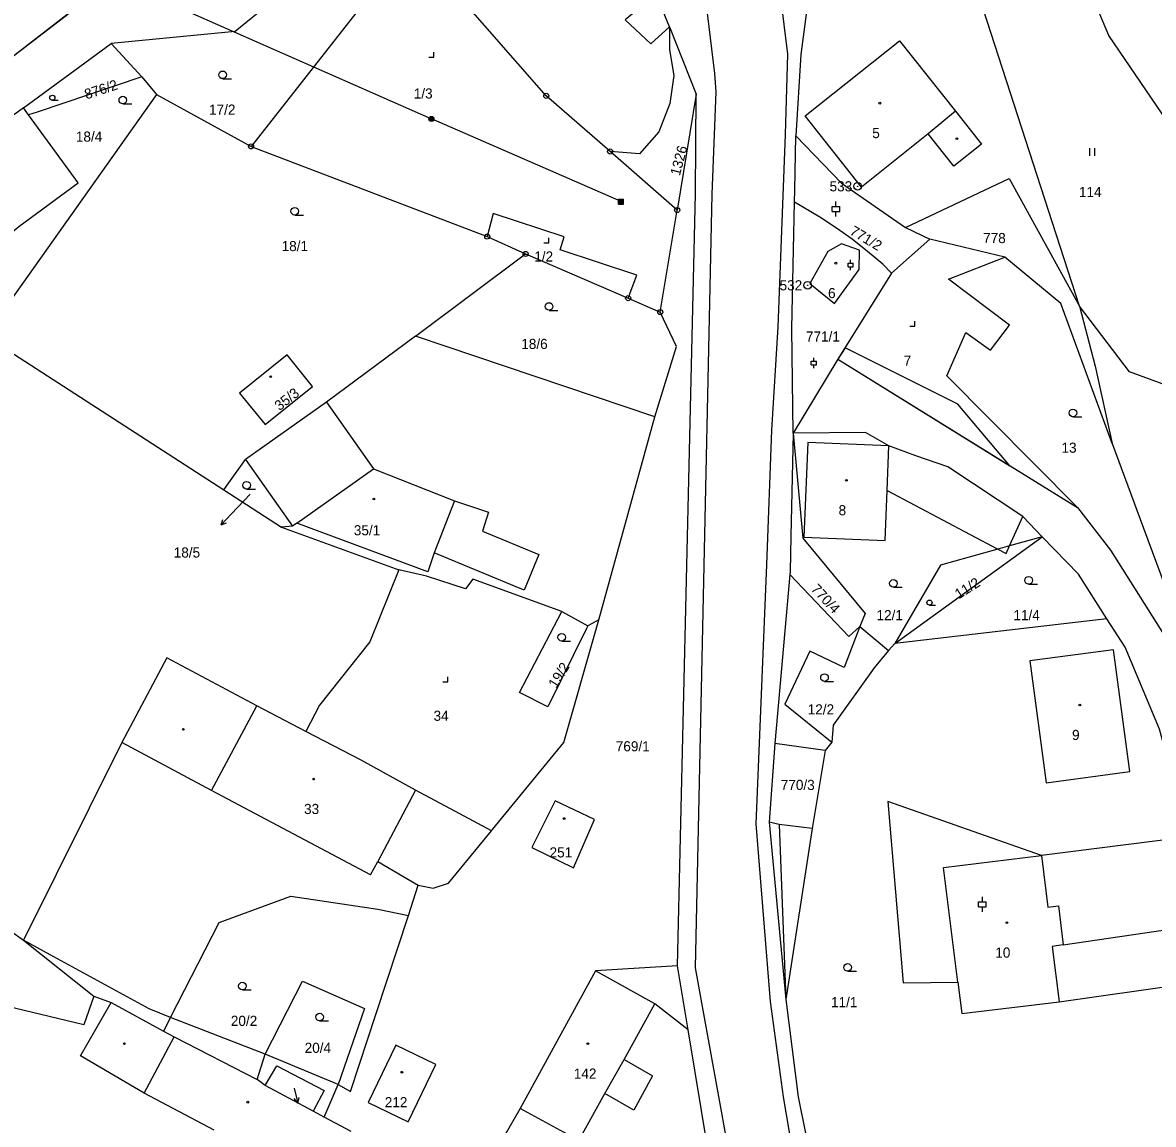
# Model space of a CAD drawing. Extents: x -745926 to -742978, y -968282 to -965689.
# Drawn here: x -744073.1 to -743961.6, y -967239.9 to -967131.3 of the extents above; entities that cross this region are included whole.
import ezdxf

# ---------------------------------------------------------------- set-up
doc = ezdxf.new("R2010")
doc.units = 0
for name, color, linetype in [('Hranice parcel', 7, 'Continuous'), ('Parcelní čísla', 7, 'Continuous'), ('Pop  PČ popisy', 7, 'Continuous'), ('Poz předměty', 7, 'Continuous'), ('Vnitřní kresba', 7, 'Continuous'), ('Věcná břemena k části', 7, 'Continuous'), ('Značky bodu BP', 7, 'Continuous'), ('Značky budov', 7, 'Continuous'), ('Značky kultur', 7, 'Continuous')]:
    doc.layers.add(name, color=color, linetype=linetype)

msp = doc.modelspace()

# ---------------------------------------------------------------- linework, layer by layer
at = {"layer": 'Hranice parcel'}
for p, q in [((-743968.9, -967159.27), (-743979.89, -967125.39)), ((-744009.34, -967131.73), (-744009.35, -967133.98)), ((-744009.34, -967131.73), (-744006.7, -967138.34)), ((-744073.05, -967139.7), (-744064.38, -967133.35)), ((-744064.38, -967133.35), (-744061.36, -967136.66)), ((-744061.36, -967136.66), (-744059.93, -967138.4)), ((-744059.93, -967138.4), (-744076.79, -967162.17)), ((-744059.93, -967138.4), (-744050.6, -967143.51)), ((-744006.7, -967138.34), (-744008.58, -967149.78)), ((-744072.54, -967140.4), (-744073.05, -967139.7)), ((-743996.87, -967142.48), (-743992.39, -967147.13)), ((-744050.6, -967143.51), (-744027.3, -967152.4)), ((-744008.58, -967149.78), (-744015.2, -967144.01)), ((-744012.29, -967144.25), (-744015.2, -967144.01)), ((-743992.39, -967147.13), (-743986.07, -967151.49)), ((-743994.5, -967150.49), (-743997, -967149.01)), ((-744010.24, -967159.84), (-744008.58, -967149.78)), ((-743986.07, -967151.49), (-743983.65, -967152.65)), ((-744027.3, -967152.4), (-744023.52, -967154.11)), ((-743983.65, -967152.65), (-743987.43, -967156)), ((-743976.26, -967154.44), (-743983.65, -967152.65)), ((-744034.39, -967162.21), (-744023.52, -967154.11)), ((-744023.52, -967154.11), (-744013.41, -967158.47)), ((-743981.81, -967156.58), (-743976.26, -967154.44)), ((-743987.43, -967156), (-743992.72, -967164.49)), ((-743987.43, -967156), (-743988.29, -967155.13)), ((-744013.41, -967158.47), (-744010.24, -967159.84)), ((-744076.79, -967162.17), (-744053.28, -967177.37)), ((-744010.78, -967170.17), (-744034.39, -967162.21)), ((-743992.72, -967164.49), (-743997.15, -967171.77)), ((-743992.72, -967164.49), (-743969.11, -967179.11)), ((-744016.31, -967190.19), (-744010.78, -967170.17)), ((-744053.28, -967177.37), (-744051.15, -967174.39)), ((-744053.28, -967177.37), (-744047.58, -967181.06)), ((-744047.58, -967181.06), (-744036.03, -967185.25)), ((-743987.1, -967192.5), (-743972.6, -967182)), ((-743991.64, -967191.84), (-743997.47, -967185.7)), ((-744019.96, -967189.37), (-744017.38, -967190.76)), ((-744016.31, -967190.19), (-744017.38, -967190.76)), ((-743966.2, -967190.1), (-743987.1, -967192.5)), ((-743990.55, -967190.85), (-743991.64, -967191.84)), ((-743990.55, -967190.85), (-743987.74, -967193.2)), ((-743987.1, -967192.5), (-743987.74, -967193.2)), ((-744043.86, -967198.58), (-744045.21, -967201.2)), ((-744084.32, -967213.62), (-744073.04, -967221.78)), ((-744008.55, -967224.29), (-744016.62, -967224.8)), ((-744049.2, -967233), (-744058.54, -967229.38)), ((-744050, -967235.5), (-744049.2, -967233)), ((-744042, -967236), (-744049.2, -967233)), ((-744043.4, -967239.2), (-744042, -967236)), ((-744040.73, -967240.63), (-744043.4, -967239.2))]:
    msp.add_line(p, q, dxfattribs=at)
for points in [[(-744009.34, -967131.73), (-744009.8, -967130.59), (-744012.89, -967120.65), (-744016.25, -967113.47), (-744022.5, -967103.98), (-744033.34, -967092.41)], [(-743949.75, -967156.45), (-743966.01, -967132.58), (-743973.69, -967114.32)], [(-744033.92, -967118.82), (-744032.36, -967116.55), (-744030.03, -967117.07), (-744029, -967116.25), (-744028.1, -967117.44), (-744025.73, -967115.63), (-744011.89, -967129.55), (-744013.71, -967131.02), (-744011.19, -967133.38), (-744009.34, -967131.73)], [(-744015.2, -967144.01), (-744021.49, -967138.52), (-744036.61, -967121.25)], [(-743994.78, -967122.23), (-743996.37, -967134.44), (-743996.87, -967142.48)], [(-744044.82, -967126.21), (-744052.16, -967132.18), (-744064.38, -967133.35)], [(-744137.82, -967186.73), (-744112.66, -967166.6), (-744088.46, -967146.5), (-744077.43, -967137.18), (-744066.14, -967128.51), (-744057.36, -967127.47)], [(-744042.64, -967127.85), (-744040.27, -967130.37), (-744050.6, -967143.51)], [(-744009.35, -967133.98), (-744008.91, -967136.5), (-744009.29, -967139.28), (-744010.4, -967142.08), (-744012.29, -967144.25)], [(-744061.36, -967136.66), (-744071.69, -967140.12), (-744072.54, -967140.4)], [(-744008.55, -967224.29), (-744006.77, -967148.18), (-744006.7, -967138.34)], [(-744073.05, -967139.7), (-744075.23, -967141.3), (-744081.28, -967145.72)], [(-744075.76, -967153.29), (-744073.49, -967151.4), (-744067.64, -967147.1), (-744072.54, -967140.4)], [(-743997, -967149.01), (-743996.98, -967147.81), (-743996.87, -967142.48)], [(-743986.07, -967151.49), (-743975.84, -967146.67), (-743968.9, -967159.27)], [(-743997.15, -967171.77), (-743997.26, -967161.45), (-743997, -967149.01)], [(-744013.41, -967158.47), (-744012.55, -967156.2), (-744020.11, -967153.69), (-744019.73, -967152.41), (-744026.73, -967150.13), (-744027.3, -967152.4)], [(-743988.29, -967155.13), (-743989.8, -967153.86), (-743991.33, -967152.64), (-743992.86, -967151.58), (-743994.5, -967150.49)], [(-743990.64, -967155.65), (-743990.59, -967153.73), (-743992.36, -967153.12), (-743993.71, -967153.87), (-743995.49, -967157.02), (-743993.06, -967158.98), (-743990.64, -967155.65)], [(-743965.7, -967172.81), (-743970.74, -967158.98), (-743976.26, -967154.44)], [(-743980.13, -967161.87), (-743977.68, -967163.58), (-743975.82, -967161.14), (-743981.81, -967156.58)], [(-743957.06, -967168.26), (-743963.99, -967165.74), (-743968.9, -967159.27)], [(-743968.9, -967159.27), (-743967.36, -967165.16), (-743965.7, -967172.81)], [(-744010.78, -967170.17), (-744008.66, -967163.25), (-744010.24, -967159.84)], [(-744034.39, -967162.21), (-744043.15, -967168.73), (-744051.15, -967174.39)], [(-743969.11, -967179.11), (-743981.98, -967166.14), (-743980.13, -967161.87)], [(-744044.54, -967167.19), (-744047.04, -967164.06), (-744051.72, -967167.83), (-744049.21, -967170.94), (-744044.54, -967167.19)], [(-743997.15, -967171.77), (-743997.36, -967181.92), (-743997.44, -967185.41), (-743997.47, -967185.7)], [(-743972.6, -967182), (-743974.5, -967180), (-743981.9, -967175.1), (-743985.04, -967174.03), (-743987.7, -967173.03), (-743990, -967171.7), (-743997.15, -967171.77)], [(-743997.15, -967171.77), (-743996.2, -967182.13), (-743990.05, -967189.56), (-743990.55, -967190.85)], [(-743987.7, -967173.03), (-743995.71, -967172.7), (-743996.09, -967182.03), (-743988.07, -967182.36), (-743987.87, -967177.44), (-743987.7, -967173.03)], [(-743965.7, -967172.81), (-743962.6, -967181.16), (-743957.8, -967194.05)], [(-744051.15, -967174.39), (-744046.51, -967180.95), (-744047.58, -967181.06)], [(-743969.11, -967179.11), (-743965.84, -967183.3), (-743960.16, -967192.32), (-743957.8, -967194.05)], [(-743972.6, -967182), (-743975.81, -967182.89), (-743976.96, -967183.21), (-743982.61, -967184.79), (-743987.1, -967192.5)], [(-743966.2, -967190.1), (-743969, -967185.67), (-743972.6, -967182)], [(-744036.03, -967185.25), (-744038.87, -967192.34), (-744043.86, -967198.58)], [(-744029.44, -967187.14), (-744033.3, -967185.89), (-744036.03, -967185.25)], [(-744019.96, -967189.37), (-744028.74, -967186.16), (-744029.44, -967187.14)], [(-743997.47, -967185.7), (-743998.94, -967202.36), (-743999.52, -967210.13), (-743997.85, -967227.62)], [(-744017.38, -967190.76), (-744017.51, -967191.03), (-744021.32, -967198.75), (-744024.14, -967197.36), (-744020.35, -967190.11), (-744019.96, -967189.37)], [(-744026.89, -967210.98), (-744026.78, -967210.85), (-744019.74, -967202.29), (-744016.63, -967191.32), (-744016.31, -967190.19)], [(-743958.88, -967211.68), (-743958.92, -967208.65), (-743961.01, -967200.97), (-743964.39, -967192.87), (-743966.2, -967190.1)], [(-743990.55, -967190.85), (-743992.11, -967194.88), (-743995.5, -967193.26), (-743997.97, -967198.5), (-743993.34, -967202.26)], [(-744045.21, -967201.2), (-744050.03, -967198.65), (-744058.89, -967193.94), (-744063.33, -967202.29), (-744073.04, -967221.78)], [(-743987.74, -967193.2), (-743989.15, -967194.91), (-743993.21, -967200.58), (-743993.34, -967202.26)], [(-743965.56, -967193.13), (-743973.79, -967194.24), (-743972.18, -967206.24), (-743963.95, -967205.14), (-743965.56, -967193.13)], [(-744026.89, -967210.98), (-744030.01, -967209.31), (-744034.38, -967206.99), (-744039.74, -967204.02), (-744045.21, -967201.2)], [(-743993.34, -967202.26), (-743993.97, -967203.07), (-743995.27, -967210.77), (-743997.85, -967227.62)], [(-744018.8, -967214.63), (-744016.72, -967209.87), (-744020.6, -967208.02), (-744022.91, -967212.62), (-744018.8, -967214.63)], [(-743958.88, -967211.68), (-743972.65, -967213.41), (-743987.8, -967208.08), (-743986.29, -967225.98), (-743980.91, -967225.9), (-743980.52, -967229.01), (-743970.92, -967227.83), (-743958.69, -967226.11)], [(-744035.06, -967219.32), (-744034.13, -967216.34), (-744032.64, -967216.63), (-744031.13, -967216.13), (-744026.89, -967210.98)], [(-744058.54, -967229.38), (-744053.74, -967220.04), (-744046.66, -967217.44), (-744038.1, -967218.7), (-744035.06, -967219.32)], [(-744042, -967236), (-744040.8, -967236.68), (-744038.26, -967229), (-744035.06, -967219.32)], [(-744073.04, -967221.78), (-744066.09, -967227.3), (-744067.08, -967230.12), (-744077.36, -967227.66), (-744081.45, -967235.81)], [(-744058.54, -967229.38), (-744060.63, -967228.52), (-744070.4, -967223.22), (-744073.04, -967221.78)], [(-744016.62, -967224.8), (-744024.05, -967238.35), (-744026.17, -967242)], [(-744019.03, -967242.88), (-744018.28, -967241.53), (-744015.71, -967236.89), (-744013.79, -967233.53), (-744010.78, -967228.05), (-744016.62, -967224.8)], [(-743996.23, -967299.83), (-744000.71, -967267.99), (-744004.21, -967250.49), (-744007.48, -967230.59), (-744008.55, -967224.29)], [(-744049.2, -967233), (-744045.53, -967225.8), (-744039.4, -967228.5), (-744042, -967236)], [(-743997.85, -967227.62), (-743996.65, -967237.2), (-743993.67, -967252.02)], [(-744035.11, -967239.68), (-744032.38, -967234.02), (-744036.33, -967232.12), (-744039.06, -967237.78), (-744035.11, -967239.68)], [(-744043.4, -967239.2), (-744044.47, -967238.63), (-744049.21, -967236.1), (-744050, -967235.5)]]:
    msp.add_lwpolyline(points, dxfattribs=at)
at = {"layer": 'Pop  PČ popisy'}
for p, q in [((-744050.68, -967177.79), (-744052.51, -967179.73)), ((-744052.51, -967179.73), (-744053.53, -967180.83)), ((-744053.53, -967180.83), (-744053.38, -967180.29)), ((-744053.53, -967180.83), (-744053.01, -967180.63)), ((-744046.34, -967236.36), (-744045.98, -967237.82)), ((-744045.98, -967237.82), (-744046.34, -967237.39)), ((-744045.98, -967237.82), (-744045.85, -967237.27))]:
    msp.add_line(p, q, dxfattribs=at)
at = {"layer": 'Poz předměty'}
for p, q in [((-744116.17, -967167.07), (-744064.17, -967126.95)), ((-744064.17, -967126.95), (-744032.81, -967140.8)), ((-744014.11, -967148.95), (-744032.81, -967140.8)), ((-744014.36, -967148.7), (-744013.86, -967148.7)), ((-744014.36, -967149.2), (-744014.36, -967148.7)), ((-744014.36, -967148.8), (-744013.86, -967148.8)), ((-744014.36, -967148.9), (-744013.86, -967148.9)), ((-744014.36, -967149), (-744013.86, -967149)), ((-744014.36, -967149.1), (-744013.86, -967149.1)), ((-744014.36, -967149.2), (-744013.86, -967149.2)), ((-744014.26, -967149.2), (-744014.26, -967148.7)), ((-744014.16, -967149.2), (-744014.16, -967148.7)), ((-744014.06, -967149.2), (-744014.06, -967148.7)), ((-744013.96, -967149.2), (-744013.96, -967148.7)), ((-744013.86, -967149.2), (-744013.86, -967148.7))]:
    msp.add_line(p, q, dxfattribs=at)
for radius in [0.25, 0.2, 0.15, 0.1, 0.05]:
    msp.add_circle((-744032.81, -967140.8), radius, dxfattribs=at)
at = {"layer": 'Vnitřní kresba'}
for p, q in [((-743997.65, -967134.42), (-743999.13, -967122.92)), ((-744005.74, -967129.28), (-744004.9, -967136.31)), ((-743995.97, -967140.49), (-743986.67, -967133.09)), ((-743986.67, -967133.09), (-743981.14, -967140.04)), ((-743997.91, -967142.34), (-743997.65, -967134.42)), ((-744004.9, -967136.31), (-744004.78, -967138.14)), ((-744004.78, -967138.14), (-744005.17, -967148.23)), ((-743990.39, -967147.51), (-743995.97, -967140.49)), ((-743981.14, -967140.04), (-743983.82, -967142.28)), ((-743981.14, -967140.04), (-743978.57, -967143.27)), ((-743998.62, -967161.31), (-743997.91, -967142.34)), ((-743983.82, -967142.28), (-743990.39, -967147.51)), ((-743981.3, -967145.45), (-743983.82, -967142.28)), ((-743978.57, -967143.27), (-743981.3, -967145.45)), ((-744005.17, -967148.23), (-744006.79, -967224.5)), ((-743999.24, -967171.48), (-743998.62, -967161.31)), ((-744043.15, -967168.73), (-744038.51, -967175.28)), ((-743999.73, -967184.77), (-743999.24, -967171.48)), ((-744046.09, -967180.65), (-744038.51, -967175.28)), ((-744038.51, -967175.28), (-744030.55, -967178.44)), ((-744030.55, -967178.44), (-744032.54, -967183.59)), ((-744030.55, -967178.44), (-744027.17, -967179.58)), ((-743987.87, -967177.44), (-743976.96, -967183.21)), ((-744046.09, -967180.65), (-744046.51, -967180.95)), ((-744033.15, -967185.44), (-744046.09, -967180.65)), ((-744027.17, -967179.58), (-744027.78, -967181.43)), ((-743975.81, -967182.89), (-743974.5, -967180)), ((-744027.78, -967181.43), (-744022.22, -967183.73)), ((-743976.15, -967183.64), (-743975.81, -967182.89)), ((-744032.54, -967183.59), (-744033.15, -967185.44)), ((-744023.68, -967187.27), (-744032.54, -967183.59)), ((-744022.22, -967183.73), (-744023.68, -967187.27)), ((-743976.96, -967183.21), (-743976.15, -967183.64)), ((-744000.8, -967210.31), (-743999.73, -967184.77)), ((-744054.48, -967207.01), (-744050.03, -967198.65)), ((-744054.48, -967207.01), (-744063.33, -967202.29)), ((-743993.97, -967203.07), (-743998.94, -967202.36)), ((-744038.83, -967215.34), (-744054.48, -967207.01)), ((-744034.38, -967206.99), (-744038.1, -967214)), ((-743999.37, -967227.81), (-744000.8, -967210.31)), ((-743998.52, -967210.35), (-743999.52, -967210.13)), ((-743995.27, -967210.77), (-743998.52, -967210.35)), ((-743998.52, -967210.35), (-743997.85, -967227.62)), ((-744038.83, -967215.34), (-744038.1, -967214)), ((-744038.1, -967214), (-744034.13, -967216.34)), ((-743982.3, -967214.6), (-743972.65, -967213.41)), ((-743972.65, -967213.41), (-743972.03, -967218.5)), ((-743980.91, -967225.9), (-743982.3, -967214.6)), ((-743972.03, -967218.5), (-743970.99, -967218.38)), ((-743970.99, -967218.38), (-743970.51, -967222.24)), ((-743970.51, -967222.24), (-743958.31, -967220.44)), ((-743970.51, -967222.24), (-743971.6, -967222.38)), ((-743971.6, -967222.38), (-743970.92, -967227.83)), ((-744006.79, -967224.5), (-743993.32, -967299.06)), ((-744066.09, -967227.3), (-744064.4, -967227.91)), ((-744067.42, -967233.16), (-744064.4, -967227.91)), ((-744064.4, -967227.91), (-744059.23, -967230.73)), ((-744007.48, -967230.59), (-744010.78, -967228.05)), ((-743998.09, -967237.22), (-743999.37, -967227.81)), ((-744058.54, -967229.38), (-744059.23, -967230.73)), ((-744059.23, -967230.73), (-744058.18, -967231.31)), ((-744061.13, -967236.84), (-744058.18, -967231.31)), ((-744058.18, -967231.31), (-744050, -967235.5)), ((-744061.13, -967236.84), (-744067.42, -967233.16)), ((-744049.21, -967236.1), (-744048.06, -967234.15)), ((-744048.06, -967234.15), (-744043.37, -967236.58)), ((-744013.79, -967233.53), (-744011, -967235.13)), ((-744011, -967235.13), (-744012.86, -967238.52)), ((-744054.24, -967240.51), (-744061.13, -967236.84)), ((-744043.37, -967236.58), (-744044.47, -967238.63)), ((-744012.86, -967238.52), (-744015.71, -967236.89)), ((-743995.59, -967252.14), (-743998.09, -967237.22)), ((-744018.28, -967241.53), (-744024.05, -967238.35))]:
    msp.add_line(p, q, dxfattribs=at)
at = {"layer": 'Věcná břemena k části'}
msp.add_lwpolyline([(-743992.02, -967163.37), (-743992.72, -967164.49), (-743975.77, -967174.99), (-743980.9, -967168.93)], close=True, dxfattribs=at)
at = {"layer": 'Značky bodu BP'}
for centre, radius in [((-744021.49, -967138.52), 0.25), ((-744021.49, -967138.52), 0.0152), ((-744050.6, -967143.51), 0.25), ((-744050.6, -967143.51), 0.0152), ((-744015.2, -967144.01), 0.25), ((-744015.2, -967144.01), 0.0152), ((-743990.78, -967147.44), 0.375), ((-743990.78, -967147.44), 0.015), ((-744008.58, -967149.78), 0.25), ((-744008.58, -967149.78), 0.0152), ((-744027.3, -967152.4), 0.25), ((-744027.3, -967152.4), 0.0152), ((-744023.52, -967154.11), 0.25), ((-744023.52, -967154.11), 0.0152), ((-743995.71, -967157.2), 0.375), ((-743995.71, -967157.2), 0.015), ((-744013.41, -967158.47), 0.25), ((-744013.41, -967158.47), 0.0152), ((-744010.24, -967159.84), 0.25), ((-744010.24, -967159.84), 0.0152)]:
    msp.add_circle(centre, radius, dxfattribs=at)
at = {"layer": 'Značky budov'}
for centre in [(-743988.59, -967139.24), (-743980.99, -967142.74), (-743992.93, -967155.02), (-744048.66, -967166.21), (-743991.89, -967176.43), (-744038.48, -967178.27), (-743968.87, -967198.58), (-744057.27, -967200.98), (-744044.42, -967205.88), (-744019.72, -967209.78), (-743976.06, -967220.04), (-744063.09, -967231.97), (-744017.39, -967231.97), (-744035.72, -967234.79), (-744050.92, -967237.74)]:
    msp.add_circle(centre, 0.0875, dxfattribs=at)
at = {"layer": 'Značky kultur'}
for p, q in [((-744033.08, -967134.7), (-744032.58, -967134.7)), ((-744032.58, -967134.7), (-744032.58, -967134.2)), ((-744053.4, -967136.83), (-744052.52, -967136.83)), ((-744070.19, -967138.96), (-744069.6, -967138.96)), ((-744063.24, -967139.32), (-744062.36, -967139.32)), ((-743967.9, -967144.43), (-743967.9, -967143.68)), ((-743967.4, -967144.43), (-743967.4, -967143.68)), ((-743993.31, -967149.43), (-743992.55, -967149.43)), ((-743993.31, -967149.93), (-743993.31, -967149.43)), ((-743992.93, -967149.43), (-743992.93, -967148.93)), ((-743992.55, -967149.93), (-743992.55, -967149.43)), ((-744046.29, -967150.28), (-744045.41, -967150.28)), ((-743993.31, -967149.93), (-743992.55, -967149.93)), ((-743992.93, -967150.43), (-743992.93, -967149.93)), ((-744021.22, -967153.02), (-744021.22, -967152.52)), ((-744021.72, -967153.02), (-744021.22, -967153.02)), ((-743991.73, -967155.03), (-743991.23, -967155.03)), ((-743991.73, -967155.37), (-743991.73, -967155.03)), ((-743991.48, -967155.03), (-743991.48, -967154.7)), ((-743991.23, -967155.37), (-743991.23, -967155.03)), ((-743991.73, -967155.37), (-743991.23, -967155.37)), ((-743991.48, -967155.7), (-743991.48, -967155.37)), ((-744021.21, -967159.67), (-744020.33, -967159.67)), ((-743985.63, -967161.24), (-743985.13, -967161.24)), ((-743985.13, -967161.24), (-743985.13, -967160.74)), ((-743995.35, -967164.69), (-743994.85, -967164.69)), ((-743995.35, -967165.03), (-743995.35, -967164.69)), ((-743995.35, -967165.03), (-743994.85, -967165.03)), ((-743995.1, -967164.69), (-743995.1, -967164.35)), ((-743995.1, -967165.36), (-743995.1, -967165.03)), ((-743994.85, -967165.03), (-743994.85, -967164.69)), ((-743969.55, -967170.16), (-743968.67, -967170.16)), ((-744051.03, -967177.29), (-744050.15, -967177.29)), ((-743987.26, -967186.97), (-743986.38, -967186.97)), ((-743973.92, -967186.67), (-743973.04, -967186.67)), ((-743983.7, -967188.73), (-743983.11, -967188.73)), ((-744019.96, -967192.28), (-744019.08, -967192.28)), ((-744031.18, -967196.31), (-744031.18, -967195.81)), ((-743994.05, -967196.26), (-743993.17, -967196.26)), ((-744031.68, -967196.31), (-744031.18, -967196.31)), ((-743978.48, -967217.98), (-743978.48, -967217.48)), ((-743978.86, -967217.98), (-743978.1, -967217.98)), ((-743978.86, -967218.48), (-743978.86, -967217.98)), ((-743978.86, -967218.48), (-743978.1, -967218.48)), ((-743978.48, -967218.98), (-743978.48, -967218.48)), ((-743978.1, -967218.48), (-743978.1, -967217.98)), ((-743991.77, -967224.83), (-743990.89, -967224.83)), ((-744051.45, -967226.67), (-744050.57, -967226.67)), ((-744043.84, -967229.73), (-744042.96, -967229.73))]:
    msp.add_line(p, q, dxfattribs=at)
for centre, radius in [((-744053.4, -967136.45), 0.375), ((-744070.19, -967138.71), 0.251), ((-744063.24, -967138.94), 0.375), ((-744046.29, -967149.9), 0.375), ((-744021.21, -967159.29), 0.375), ((-743969.55, -967169.78), 0.375), ((-744051.03, -967176.91), 0.375), ((-743987.26, -967186.59), 0.375), ((-743973.92, -967186.29), 0.375), ((-743983.7, -967188.48), 0.251), ((-744019.96, -967191.9), 0.375), ((-743994.05, -967195.88), 0.375), ((-743991.77, -967224.45), 0.375), ((-744051.45, -967226.29), 0.375), ((-744043.84, -967229.35), 0.375)]:
    msp.add_circle(centre, radius, dxfattribs=at)

# ---------------------------------------------------------------- texts
at = {"layer": 'Parcelní čísla'}
for s, rotation, p in [('876/2', 18, (-744066.83, -967138.88)), ('1326', 75, (-744008.32, -967146.46)), ('771/2', 329, (-743991.64, -967152.12)), ('35/3', 38, (-744047.79, -967169.62)), ('11/2', 32, (-743980.81, -967188.17)), ('770/4', 313, (-743995.45, -967187.21)), ('19/2', 58, (-744020.51, -967197))]:
    msp.add_text(s, height=1, rotation=rotation, dxfattribs=at).set_placement(p)
for s, p in [('1/3', (-744034.55, -967138.79)), ('17/2', (-744054.74, -967140.38)), ('18/4', (-744067.87, -967143.04)), ('5', (-743989.34, -967142.69)), ('114', (-743968.96, -967148.5)), ('18/1', (-744047.58, -967153.83)), ('778', (-743978.41, -967153.04)), ('1/2', (-744022.67, -967154.86)), ('6', (-743993.7, -967158.47)), ('771/1', (-743995.88, -967162.75)), ('18/6', (-744023.95, -967163.48)), ('7', (-743986.24, -967165.13)), ('13', (-743970.68, -967173.71)), ('8', (-743992.66, -967179.88)), ('35/1', (-744040.46, -967181.85)), ('18/5', (-744058.22, -967184.04)), ('12/1', (-743988.92, -967190.22)), ('11/4', (-743975.42, -967190.22)), ('12/2', (-743995.71, -967199.51)), ('34', (-744032.6, -967200.14)), ('9', (-743969.64, -967202.03)), ('769/1', (-744014.63, -967203.15)), ('770/3', (-743998.36, -967206.96)), ('33', (-744045.37, -967209.33)), ('251', (-744021.16, -967213.61)), ('10', (-743977.21, -967223.49)), ('11/1', (-743993.41, -967228.38)), ('20/2', (-744052.59, -967230.22)), ('20/4', (-744045.31, -967232.88)), ('142', (-744018.77, -967235.42)), ('212', (-744037.41, -967238.24))]:
    msp.add_text(s, height=1, dxfattribs=at).set_placement(p)
at = {"layer": 'Značky bodu BP'}
for s, p in [('533', (-743993.55, -967147.94)), ('532', (-743998.48, -967157.7))]:
    msp.add_text(s, height=1, dxfattribs=at).set_placement(p)

doc.saveas('drawing.dxf')
